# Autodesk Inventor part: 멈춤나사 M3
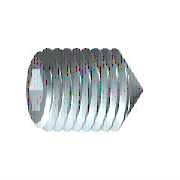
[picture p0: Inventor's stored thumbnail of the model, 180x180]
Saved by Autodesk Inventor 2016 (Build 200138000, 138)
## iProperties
IsCustomPart: 1
Created: 2012-02
Part Number: 멈춤나사 M3
Material: 강철, 연강
Description: 6각 소켓 머리 없는 멈춤 나사
Document SubType Name: Modeling
Standard: KS B 1028
Designer: mduedu
Standards Organization: KS
Language: ko-KR
Size Designation: 원추점 M3x6
Categories: <MemberInstance><Categories><Category DisplayName="조임쇠" InternalName="e4da775c-781d-43d5-af7c-5136215cf5a6" Mnemonic="FSTN"><Category DisplayName="볼트" InternalN
Density: 1 g/cm^3
Appearance: 노란색
Author: mduedu
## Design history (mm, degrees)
sketch "스케치1"
  geometry: L1 (0, 0)-(3.5, 0); L2 (6, 0.866)-(6, 1.5); L3 (6, 1.5)-(0, 1.5); L4 (6, 0.866)-(4, 0.866); L5 (4, 0.866)-(3.5, 0); L6 (0, -0.3)-(0, 1.8) reference; L7 (0, 1.5)-(0, 0)
  constraints: 13 end point, 3 parallel, 1 collinear, 1 perpendicular, 1 point on line
  dimensions: "d0" = 2 distance of L2.start L4.end (= INTI); "d1" = 60 deg angle of L5 L1; "d2" = 3 diameter of L3 L1 (= NND); "d3" = 1.73205 diameter of L4 L1 (= 1.1547 x SW); "d5" = 6 distance from line of L2 L3.end (= NLG)
revolve "본체" sketch "스케치1" stored, may be unused: angle "d6" = 90 deg
sketch "스케치2"
  geometry: L1 (-0.433, 0.75)-(0.433, 0.75); L2 (0.433, 0.75)-(0.866, 0); L3 (0.866, 0)-(0.433, -0.75); L4 (0.433, -0.75)-(-0.433, -0.75); L5 (-0.433, -0.75)-(-0.866, 0); L6 (-0.866, 0)-(-0.433, 0.75); 3 further points
  constraints: 12 end point, 1 coincident, 1 horizontal, 13 other
extrude "슬롯" join sketch "스케치2" taper "d7" = 0 deg; stored distance "d21" = 10
workaxis "Work Axis1"
workplane "Work Plane1"
body "Solid1"
feature "스레드" dims "d12" = 6 (= NLG), "d13" = 0
chamfer "모따기1" distance "d8" = 1.35 (computed from NND, SPD, FAWI); stored, may be unused: angle "d9" = 45 deg (= FAWI), second distance "d34" = 1.35 (computed from NND, SPD, FAWI)
chamfer "모따기2" distance "d10" = 0.30673 (= -0.5 x GD1 + 0.5 x NND); stored, may be unused: angle "d11" = 45 deg (= FAWI), second distance "d35" = 0.30673 (= -0.5 x GD1 + 0.5 x NND)
other parameters: "NND" = 3 [user parameter; used in 5 equation terms], "NLG" = 6 [user parameter; used in 2 equation terms], "INTI" = 2 [user parameter; used in 1 equation term], "FAWI" = 45 deg [user parameter; used in 4 equation terms], "SW" = 1.5 [user parameter; used in 2 equation terms], "GD1" = 2.38655 (= THREADDIA - 1.2269 x PTC) [user parameter; used in 2 equation terms], "d4" = 0, "FAWI1" = 45 deg [user parameter], "SPD" = 0.3 [user parameter; used in 2 equation terms], "d36" = 0, "d37" = 0, "GUL" = 0.30673 (= 0.61345 x PTC) [user parameter], "TOA" = 30 deg [user parameter], "THREADDIA" = 3 [user parameter; used in 1 equation term], "PTC" = 0.5 [user parameter; used in 4 equation terms], "GAL" = 0.30673 (= 0.61345 x PTC) [user parameter], "E0" = 1.7325 (= 1.155 x SW) [user parameter]
